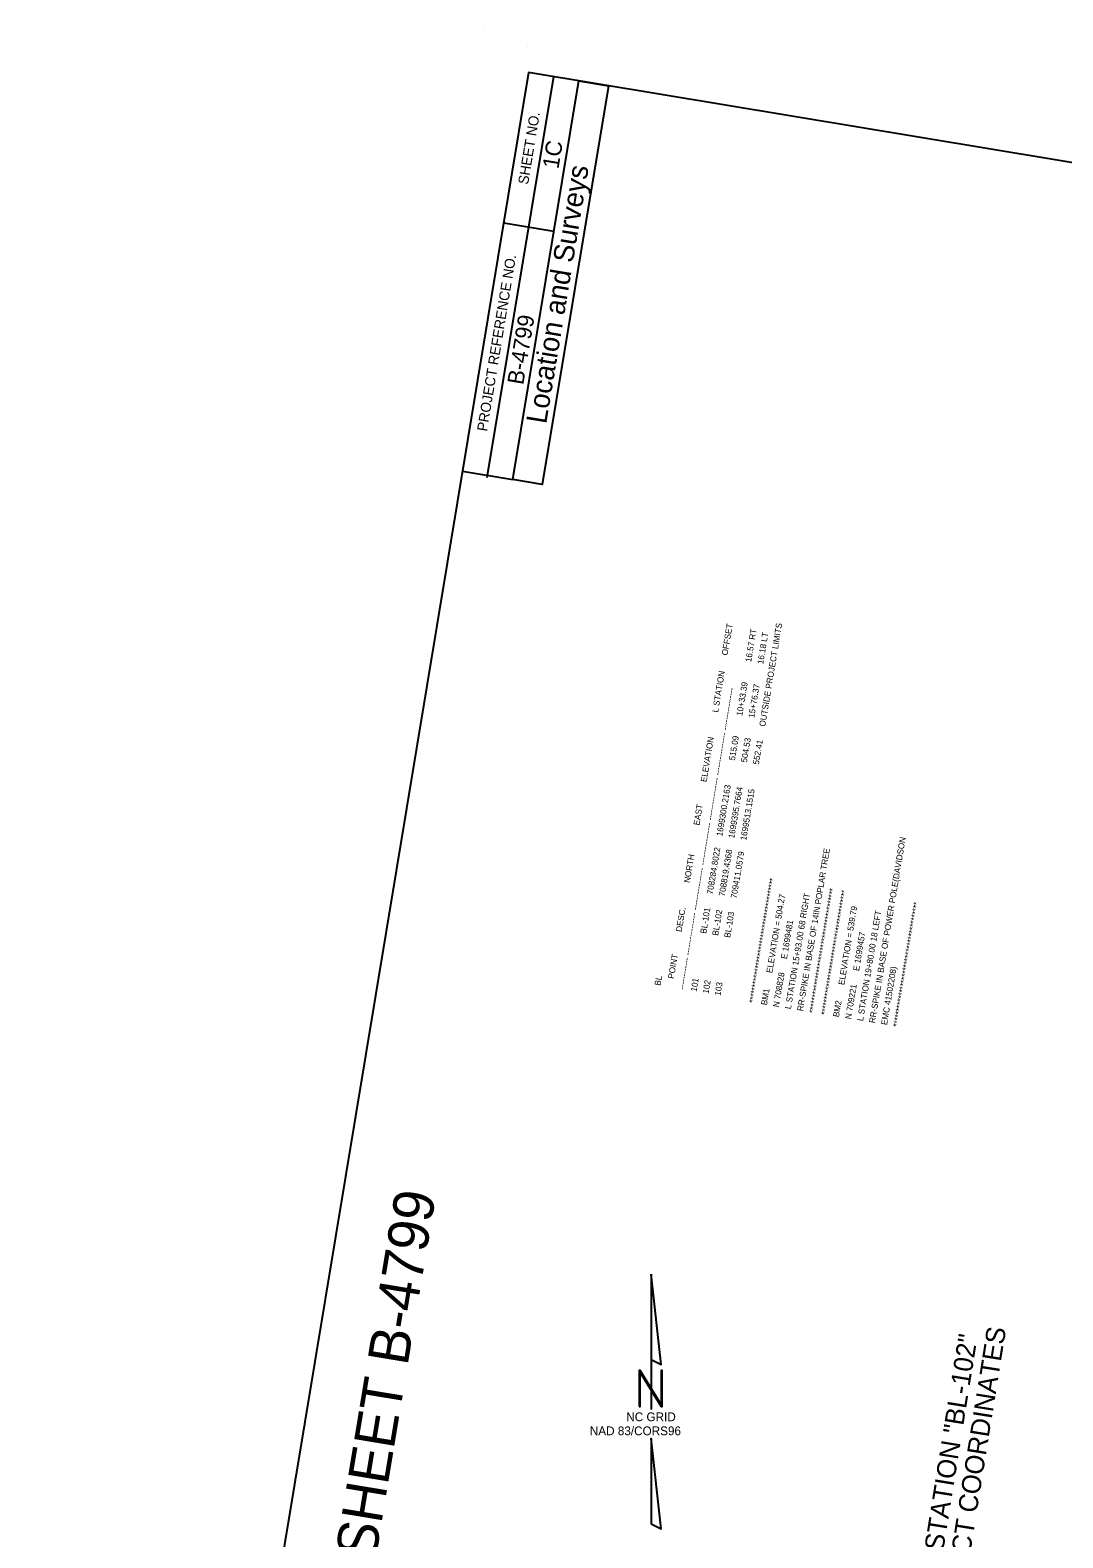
# Model space of a CAD drawing. Extents: x 1698609 to 1700392, y 707479 to 710040.
# Drawn here: x 1698609 to 1699316, y 709008 to 710040 of the extents above; entities that cross this region are included whole.
import ezdxf

# ---------------------------------------------------------------- set-up
doc = ezdxf.new("R2010")
doc.units = 0
for name, color, linetype in [('CTL North Arrow NAD 83 NSRS 2007 CELL', 7, 'Continuous'), ('CTL Sheet Border CELL', 7, 'Continuous'), ('CTL Sheet Text', 7, 'Continuous')]:
    doc.layers.add(name, color=color, linetype=linetype)

msp = doc.modelspace()

# ---------------------------------------------------------------- linework, layer by layer
at = {"layer": 'CTL North Arrow NAD 83 NSRS 2007 CELL'}
msp.add_line((1699034.5, 709100.9), (1699034.5, 709100.9), dxfattribs=at)
for points in [[(1699034.4, 709188.2), (1699034.4, 709129.9), (1699041.2, 709126.5)], [(1699026.1, 709097.7), (1699026.8, 709097.7), (1699026.8, 709121), (1699041.2, 709097.7), (1699041.9, 709097.7), (1699041.9, 709122.4), (1699041.2, 709122.4), (1699041.2, 709099), (1699026.8, 709122.4), (1699026.1, 709122.4)], [(1699034.4, 709017.4), (1699041.2, 709014), (1699034.4, 709075.7)]]:
    msp.add_lwpolyline(points, close=True, dxfattribs=at)
msp.add_lwpolyline([(1699034.4, 709129.9), (1699034.4, 709095.6)], dxfattribs=at)
at = {"layer": 'CTL Sheet Border CELL'}
for p, q in [((1698920, 710040.3), (1698920, 710040.3)), ((1698949.7, 710029.1), (1698949.7, 710029.1)), ((1698949.7, 710029.1), (1698949.7, 710029.1)), ((1698922.1, 709733.9), (1698967.6, 710008.5)), ((1698933.4, 709908.4), (1698967.7, 709902.7)), ((1698905.2, 709738.3), (1698939.5, 709732.6))]:
    msp.add_line(p, q, dxfattribs=at)
for points in [[(1698950.4, 710011.3), (1698609.1, 707952.4), (1700050.3, 707713.5), (1700391.6, 709772.4)], [(1698939.5, 709732.6), (1698984.8, 710005.6), (1699005, 710002.3), (1698959.7, 709729.2)]]:
    msp.add_lwpolyline(points, close=True, dxfattribs=at)

# ---------------------------------------------------------------- texts
at = {"layer": 'CTL North Arrow NAD 83 NSRS 2007 CELL'}
for s, p in [('NC GRID', (1699017.3, 709087.6)), (' NAD 83/CORS96', (1698990.1, 709078))]:
    msp.add_text(s, height=6, dxfattribs=at).set_placement(p)
at = {"layer": 'CTL Sheet Border CELL'}
for s, height, p in [('SHEET NO.', 6.96, (1698950, 709934.3)), ('1C', 11.13, (1698970.8, 709944.9)), ('Location and Surveys', 13.913, (1698962.4, 709770.2)), ('PROJECT REFERENCE NO.', 6.957, (1698921.9, 709765.2)), ('B-4799', 11.13, (1698946.7, 709797)), ('SURVEY CONTROL SHEET B-4799', 27.826, (1698787.3, 708641.5))]:
    msp.add_text(s, height=height, rotation=80.5874, dxfattribs=at).set_placement(p)
at = {"layer": 'CTL Sheet Text'}
for s, height, rotation, p in [('    POINT          DESC.           NORTH             EAST          ELEVATION           L STATION       OFFSET', 4.1667, 80.5874, (1699048.9, 709384.3)), ('101                    BL-101      708284.8022     1699300.2163           515.09         10+33.39         16.57 RT', 4.1667, 80.5874, (1699065.4, 709381.6)), ('102                    BL-102      708819.4368     1699395.7664           504.53         15+76.37         16.18 LT', 4.1667, 80.5874, (1699073.6, 709380.2)), ('103                    BL-103      709411.0579     1699513.1515           552.41      OUTSIDE PROJECT LIMITS                 ', 4.1667, 80.5874, (1699081.8, 709378.8)), ('------------ ---------------- ---------------- ---------------- ---------------- ---------------- ----------------', 4.1667, 80.5874, (1699057.1, 709382.9)), ('RR-SPIKE IN BASE OF POWER POLE(DAVIDSON', 4.167, 80.5874, (1699187.6, 709360)), ('RR-SPIKE IN BASE OF 14IN POPLAR TREE', 4.167, 80.5874, (1699138.3, 709368.2)), ('****************************************', 4.167, 80.5874, (1699105.4, 709373.7)), ('****************************************', 4.167, 80.5874, (1699146.5, 709366.8)), ('BM1       ELEVATION = 504.27', 4.167, 80.5874, (1699113.6, 709372.3)), ('L STATION 15+93.00 68 RIGHT', 4.167, 80.5874, (1699130, 709369.6)), ('****************************************', 4.167, 80.5874, (1699154.7, 709365.5)), ('****************************************', 4.167, 80.5874, (1699204, 709357.3)), ('BM2       ELEVATION = 539.79', 4.167, 80.5874, (1699162.9, 709364.1)), ('L STATION 19+80.00 18 LEFT', 4.167, 80.5874, (1699179.4, 709361.4)), ('N 708828      E 1699481', 4.167, 80.5874, (1699121.8, 709370.9)), ('N 709221      E 1699457', 4.167, 80.5874, (1699171.2, 709362.7)), ('BL', 4.17, 80.5874, (1699040.7, 709385.7)), ('EMC 41502208)', 4.167, 80.5874, (1699195.8, 709358.7)), ('NCDOT BASELINE STATION "BL-102"', 13.104, 80.8935, (1699209.3, 708842.5)), ('LOCALIZED PROJECT COORDINATES', 13.104, 80.9052, (1699227.3, 708837.7))]:
    msp.add_text(s, height=height, rotation=rotation, dxfattribs=at).set_placement(p)

doc.saveas('drawing.dxf')
